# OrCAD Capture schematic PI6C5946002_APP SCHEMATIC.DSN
size B; title: PI6C5946002 Application Schematic; rev: 1.0; note: Diodes Inc. Clock IC Application Engineering
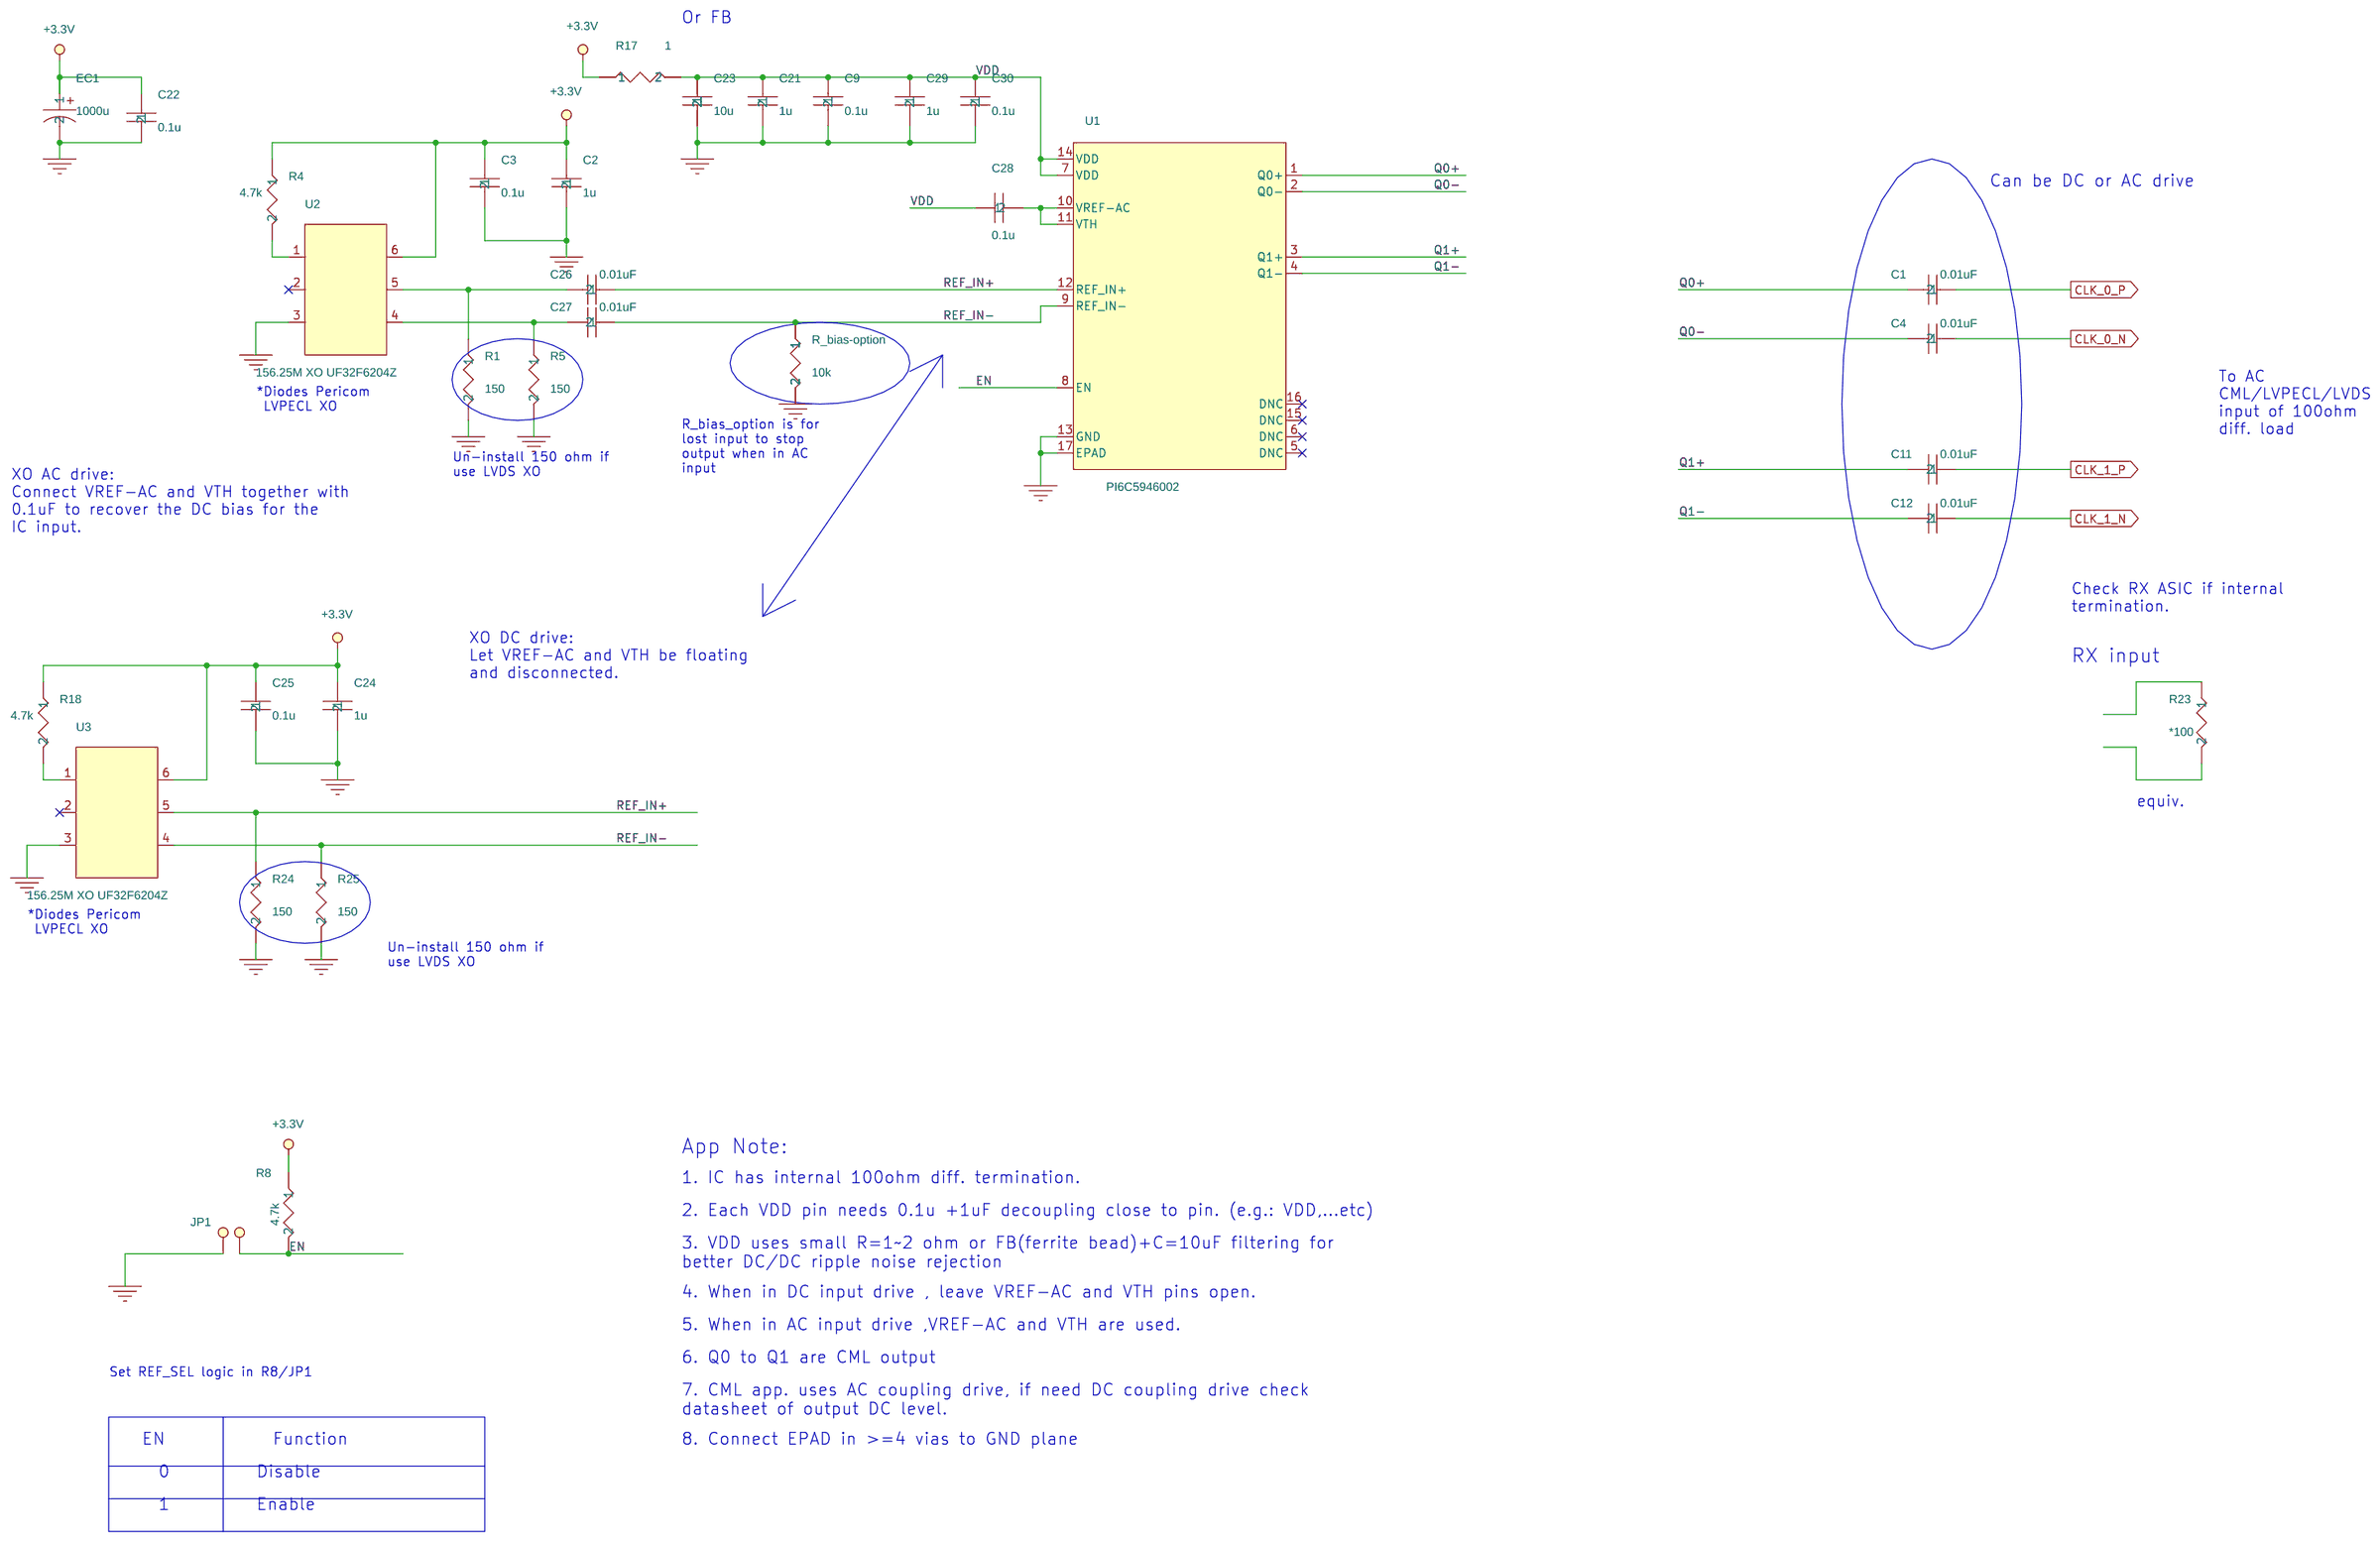
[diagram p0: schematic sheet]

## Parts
C1  0.01uF  [CC_0402]
C2  1u  [CC_0402]
C3  0.1u  [CC_0402]
C4  0.01uF  [CC_0402]
C9  0.1u  [CC_0402]
C11  0.01uF  [CC_0402]
C12  0.01uF  [CC_0402]
C21  1u  [CC_0805]
C22  0.1u  [CC_0402]
C23  10u  [CC_0805]
C24  1u  [CC_0402]
C25  0.1u  [CC_0402]
C26  0.01uF  [CC_0402]
C27  0.01uF  [CC_0402]
C28  0.1u  [CC_0402]
C29  1u  [CC_0805]
C30  0.1u  [CC_0402]
EC1  1000u  [CAP1000UF]
JP1  2x1 Pin Header  [2x1 Pin Header]
R1  150  [R_0402]
R4  4.7k  [R_0402]
R5  150  [R_0402]
R8  4.7k  [R_0402]
R17  1  [R_0402]
R18  4.7k  [R_0402]
R23  *100  [R_0402]
R24  150  [R_0402]
R25  150  [R_0402]
R_bias-option  10k  [R_0402]
U1  PI6C5946002
U2  156.25M XO UF32F6204Z  [XO 5X7]
U3  156.25M XO UF32F6204Z  [XO 5X7]

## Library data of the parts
C1 = C_10n_0402_2
C2 = C_0.1u_0402_4
C3 = C_0.1u_0402_3
C4 = C_10n_0402_3
C9 = C_0.1u_0402_2
C11 = C_10n_0402_4
C12 = C_10n_0402_5
C21 = C_1.0u_0805_1
C22 = C_0.1u_0402_1
C23 = C_1.0u_0805
C24 = C_0.1u_0402_7
C25 = C_0.1u_0402_5
C26 = C_10n_0402_1
C27 = C_10n_0402
C28 = C_0.1u_0402
C29 = C_1.0u_0805_2
C30 = C_0.1u_0402_6
EC1 = C_alum_1000u
JP1 = 2x1_Pin_Header
R1 = R_0402_6
R4 = R_0402
R5 = R_0402_5
R8 = R_0402_1
R17 = R_0402_2
R18 = R_0402_4
R23 = R_0
R24 = R_0402_8
R25 = R_0402_7
R_bias-option = R_0402_3
U1 = PI6C4911504-03_7
U2 U3 = XO_5X7

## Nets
+3.3V: C2.1 C3.1 C22.1 C24.1 C25.1 EC1.1 R4.1 R8.1 R17.1 R18.1 U2.6 U3.6
GND: C2.2 C3.2 C9.2 C21.2 C22.2 C23.2 C24.2 C25.2 C29.2 C30.2 EC1.2 JP1.1 R1.2 R5.2 R24.2 R25.2 R_bias-option.2 U1.13(GND) U1.17(EPAD) U2.3 U3.3
VDD: C9.1 C21.1 C23.1 C28.1 C29.1 C30.1 R17.2 U1.7(VDD) U1.14(VDD)
CLK_0_N: C4.1
CLK_0_P: C1.1
CLK_1_N: C12.1
CLK_1_P: C11.1
EN: JP1.2 R8.2 U1.8(EN)
Q0+: C1.2 U1.1(Q0+)
Q0-: C4.2 U1.2(Q0-)
Q1+: C11.2 U1.3(Q1+)
Q1-: C12.2 U1.4(Q1-)
REF_IN+: C26.1 R24.1 U1.12(REF_IN+) U3.5
REF_IN-: C27.1 R25.1 R_bias-option.1 U1.9(REF_IN-) U3.4
N4608823: R4.2 U2.1
N4608911: C26.2 R1.1 U2.5
N4608919: C27.2 R5.1 U2.4
N4609914: R18.2 U3.1
N4640816: C28.2 U1.10(VREF-AC) U1.11(VTH)

Not connected (* = marked no-connect by the designer): R23 1 2; U1 5(DNC)* 6(DNC)* 15(DNC)* 16(DNC)*; U2 2*; U3 2*

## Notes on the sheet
- Or FB
- Can be DC or AC drive
- To AC
  CML/LVPECL/LVDS
  input of 100ohm
  diff. load
- *Diodes Pericom
   LVPECL XO
- R_bias_option is for
  lost input to stop
  output when in AC
  input
- Un-install 150 ohm if
  use LVDS XO
- XO AC drive:
  Connect VREF-AC and VTH together with
  0.1uF to recover the DC bias for the
  IC input.
- Check RX ASIC if internal
  termination.
- XO DC drive:
  Let VREF-AC and VTH be floating
  and disconnected.
- RX input
- equiv.
- *Diodes Pericom
   LVPECL XO
- Un-install 150 ohm if
  use LVDS XO
- App Note:
- 1. IC has internal 100ohm diff. termination.
- 2. Each VDD pin needs 0.1u +1uF decoupling close to pin. (e.g.: VDD,...etc)
- 3. VDD uses small R=1~2 ohm or FB(ferrite bead)+C=10uF filtering for
  better DC/DC ripple noise rejection
- 4. When in DC input drive , leave VREF-AC and VTH pins open.
- 5. When in AC input drive ,VREF-AC and VTH are used.
- Set REF_SEL logic in R8/JP1
- 6. Q0 to Q1 are CML output
- 7. CML app. uses AC coupling drive, if need DC coupling drive check
  datasheet of output DC level.
- EN
- Function
- 8. Connect EPAD in >=4 vias to GND plane
- 0
- Disable
- 1
- Enable
